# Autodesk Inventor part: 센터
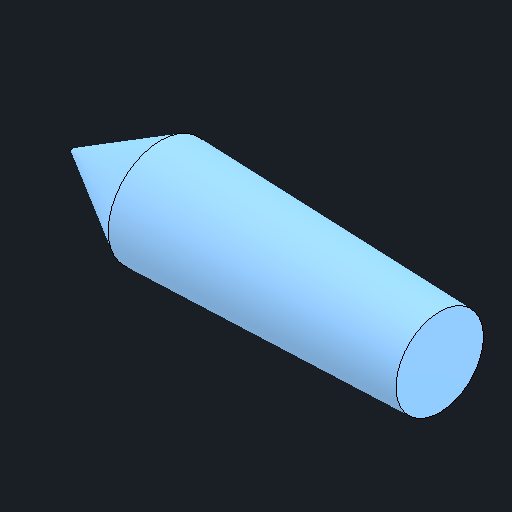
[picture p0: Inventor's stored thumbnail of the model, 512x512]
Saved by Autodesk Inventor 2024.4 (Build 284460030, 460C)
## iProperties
Created: 2026-08
Part Number: 센터
Material: 스테인리스강
Document SubType Name: Modeling
Designer: user
Density: 8.08 g/cm^3
Appearance: 기본값
Author: jhkim
Sending System: Autodesk Inventor 2027
Preprocessor: ST-DEVELOPER v20.1
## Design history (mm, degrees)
feature "솔리드1"
node "솔리드2"
